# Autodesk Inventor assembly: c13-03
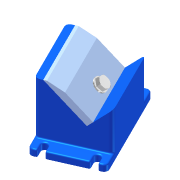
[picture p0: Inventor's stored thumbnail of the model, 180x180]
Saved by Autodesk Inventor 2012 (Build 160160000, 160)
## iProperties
Created: 2010-11
Part Number: c13-03
Document SubType Name: Assembly
Designer: Beta-8540w
Author: Beta-8540w
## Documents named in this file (5)
- C:\Users\VMuser\Desktop\Inventor 2012 Essentials\Assemblies\Chapter 13\c13-03.iam
- C:\Users\VMuser\Desktop\Inventor 2012 Essentials\Content Center Files\en-US\ISO 4017\ISO 4017 - M10 x 35ISO.ipt
- C:\Users\VMuser\Desktop\Inventor 2012 Essentials\Parts\Chapter 13\c13-02.ipt
- C:\Users\VMuser\Desktop\Inventor 2012 Essentials\Content Center Files\en-US\ISO 7091\ISO 7091 - ST 10 - 100 HV.ipt
- C:\Users\VMuser\Desktop\Inventor 2012 Essentials\Parts\Chapter 13\c13-01.ipt
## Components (4 placed, 4 different names)
1. c13-01:1 — Insert:1, Angle:1
2. c13-02:1 — Insert:1, Angle:1, Insert:2
3. ISO 4017 M10 x 35:1 — Insert:3
4. ISO 7091 ST 10 - 100 HV:1 — Insert:2, Insert:3
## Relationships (4: Insert 3, Angle 1)
- Insert:1: c13-01:1 ↔ c13-02:1
- Angle:1: c13-01:1 ↔ c13-02:1
- Insert:2: c13-02:1 ↔ ISO 7091 ST 10 - 100 HV:1
- Insert:3: ISO 4017 M10 x 35:1 ↔ ISO 7091 ST 10 - 100 HV:1
